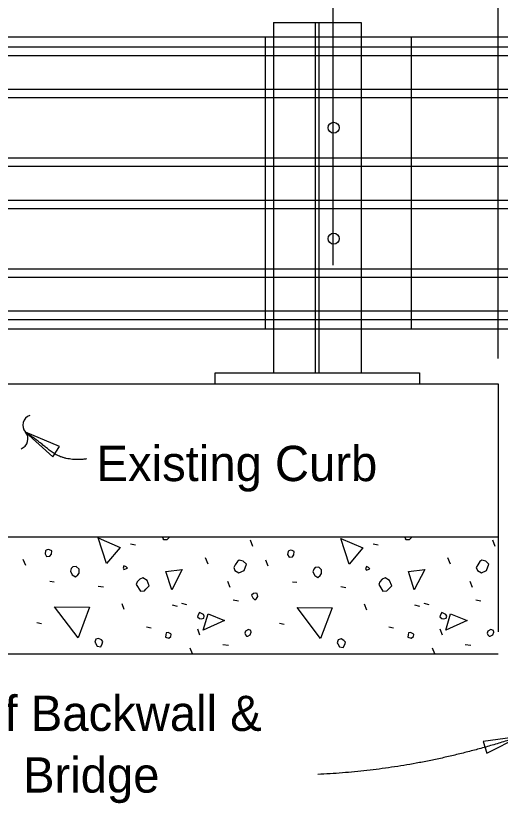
# Model space of a CAD drawing. Extents: x 21526.6 to 21595.9, y 56117 to 56157.3.
# Drawn here: x 21532.854 to 21535.621, y 56132.816 to 56137.312 of the extents above; entities that cross this region are included whole.
import ezdxf

# ---------------------------------------------------------------- set-up
doc = ezdxf.new("R2010")
doc.units = 0
for name, color, linetype in [('AdhocPoint_dp', 7, 'Continuous'), ('Border', 7, 'Continuous'), ('Patterning', 7, 'Continuous'), ('PlotBorder_dp', 7, 'Continuous'), ('SheetBorder_dp', 7, 'Continuous'), ('TextMisc', 7, 'Continuous')]:
    doc.layers.add(name, color=color, linetype=linetype)

msp = doc.modelspace()

# ---------------------------------------------------------------- linework, layer by layer
at = {"layer": 'AdhocPoint_dp'}
for p, q in [((21527.2426, 56135.21), (21535.6096, 56135.21)), ((21535.6096, 56135.2099), (21535.6096, 56133.7934)), ((21535.6096, 56134.335), (21527.2426, 56134.335)), ((21527.2426, 56133.6684), (21535.6096, 56133.6684))]:
    msp.add_line(p, q, dxfattribs=at)
at = {"layer": 'Patterning'}
for p, q in [((21534.6672, 56135.8883), (21534.6672, 56140.7989)), ((21534.2788, 56137.1891), (21534.2788, 56135.5224)), ((21535.1121, 56137.1891), (21535.1121, 56135.5224)), ((21534.1592, 56137.1336), (21541.6829, 56137.1336)), ((21534.1592, 56137.0854), (21541.6829, 56137.0854)), ((21534.1592, 56136.8926), (21541.6829, 56136.8926)), ((21534.1592, 56136.8444), (21541.6829, 56136.8444)), ((21534.1592, 56136.5004), (21541.6829, 56136.5004)), ((21534.1592, 56136.4522), (21541.6829, 56136.4522)), ((21534.1592, 56136.2594), (21541.6829, 56136.2594)), ((21534.1592, 56136.2112), (21541.6829, 56136.2112)), ((21534.1592, 56135.8673), (21541.6829, 56135.8673)), ((21534.1592, 56135.8191), (21541.6829, 56135.8191)), ((21534.1592, 56135.6262), (21541.6829, 56135.6262)), ((21534.1592, 56135.578), (21541.6829, 56135.578)), ((21533.5102, 56134.2973), (21533.5385, 56134.2902)), ((21534.2085, 56134.2814), (21534.1943, 56134.3167)), ((21534.8945, 56134.2973), (21534.9228, 56134.2902)), ((21535.5928, 56134.2814), (21535.5786, 56134.3167)), ((21532.9116, 56134.1724), (21532.8974, 56134.2077)), ((21533.9522, 56134.1806), (21533.938, 56134.216)), ((21534.2962, 56134.1689), (21534.2821, 56134.2042)), ((21535.3364, 56134.1806), (21535.3223, 56134.216)), ((21533.0495, 56134.084), (21533.0742, 56134.0805)), ((21534.0777, 56134.048), (21534.0653, 56134.0816)), ((21534.4341, 56134.0805), (21534.4589, 56134.0769)), ((21535.462, 56134.048), (21535.4496, 56134.0816)), ((21533.3252, 56134.0557), (21533.3553, 56134.0504)), ((21534.7099, 56134.0522), (21534.74, 56134.0469)), ((21534.0965, 56133.9762), (21534.1265, 56133.9709)), ((21535.4808, 56133.9762), (21535.5108, 56133.9709)), ((21533.4737, 56133.9214), (21533.4613, 56133.955)), ((21533.7477, 56133.9479), (21533.776, 56133.9408)), ((21533.8001, 56133.9579), (21533.8284, 56133.9508)), ((21534.8584, 56133.9178), (21534.846, 56133.9514)), ((21535.132, 56133.9479), (21535.1603, 56133.9408)), ((21535.1844, 56133.9579), (21535.2127, 56133.9508)), ((21532.9752, 56133.8471), (21533.0017, 56133.8418)), ((21534.3599, 56133.8436), (21534.3864, 56133.8383)), ((21533.601, 56133.8224), (21533.6275, 56133.8171)), ((21533.9062, 56133.7753), (21533.8938, 56133.8089)), ((21534.9853, 56133.8224), (21535.0118, 56133.8171)), ((21535.2905, 56133.7753), (21535.2781, 56133.8089)), ((21534.0364, 56133.7216), (21534.0682, 56133.7181)), ((21535.4207, 56133.7216), (21535.4525, 56133.7181)), ((21533.8627, 56133.6684), (21533.8496, 56133.701)), ((21535.247, 56133.6684), (21535.2339, 56133.701))]:
    msp.add_line(p, q, dxfattribs=at)
for points in [[(21533.373, 56134.1848), (21533.3252, 56134.3315), (21533.4507, 56134.2767), (21533.373, 56134.1848)], [(21533.6927, 56134.335), (21533.6923, 56134.3344), (21533.6976, 56134.322), (21533.6941, 56134.3256)], [(21533.6976, 56134.322), (21533.7188, 56134.322), (21533.7294, 56134.3326), (21533.7288, 56134.335)], [(21535.077, 56134.335), (21535.0766, 56134.3344), (21535.0819, 56134.322), (21535.0784, 56134.3256)], [(21535.0819, 56134.322), (21535.1031, 56134.322), (21535.1137, 56134.3326), (21535.1131, 56134.335)], [(21534.7576, 56134.1812), (21534.7099, 56134.328), (21534.8354, 56134.2731), (21534.7576, 56134.1812)], [(21533.0212, 56134.2396), (21533.03, 56134.2237), (21533.0495, 56134.2254), (21533.0583, 56134.2378), (21533.0601, 56134.2572), (21533.0477, 56134.2625), (21533.0389, 56134.2643), (21533.0282, 56134.2608), (21533.0247, 56134.2572), (21533.0212, 56134.2396)], [(21534.4059, 56134.236), (21534.4147, 56134.2201), (21534.4341, 56134.2219), (21534.443, 56134.2343), (21534.4447, 56134.2537), (21534.4324, 56134.259), (21534.4235, 56134.2608), (21534.4129, 56134.2572), (21534.4094, 56134.2537), (21534.4059, 56134.236)], [(21534.106, 56134.1435), (21534.1289, 56134.1311), (21534.159, 56134.1435), (21534.1714, 56134.1806), (21534.1537, 56134.1983), (21534.1307, 56134.2036), (21534.1201, 56134.1965), (21534.1077, 56134.1771), (21534.0989, 56134.1612), (21534.106, 56134.1435)], [(21535.4902, 56134.1435), (21535.5132, 56134.1311), (21535.5433, 56134.1435), (21535.5557, 56134.1806), (21535.538, 56134.1983), (21535.515, 56134.2036), (21535.5044, 56134.1965), (21535.492, 56134.1771), (21535.4832, 56134.1612), (21535.4902, 56134.1435)], [(21533.1661, 56134.1406), (21533.1767, 56134.1194), (21533.1944, 56134.1087), (21533.2086, 56134.1194), (21533.2156, 56134.13), (21533.2156, 56134.1512), (21533.1997, 56134.1671), (21533.1803, 56134.1653), (21533.1714, 56134.1565), (21533.1661, 56134.1406)], [(21533.472, 56134.1494), (21533.4914, 56134.1582), (21533.4843, 56134.1653), (21533.472, 56134.1706), (21533.4667, 56134.1582), (21533.472, 56134.1494)], [(21534.5508, 56134.137), (21534.5614, 56134.1158), (21534.5791, 56134.1052), (21534.5932, 56134.1158), (21534.6003, 56134.1264), (21534.6003, 56134.1476), (21534.5844, 56134.1635), (21534.5649, 56134.1618), (21534.5561, 56134.1529), (21534.5508, 56134.137)], [(21534.8566, 56134.1459), (21534.8761, 56134.1547), (21534.869, 56134.1618), (21534.8566, 56134.1671), (21534.8513, 56134.1547), (21534.8566, 56134.1459)], [(21533.7453, 56134.0339), (21533.7117, 56134.1382), (21533.8054, 56134.1505), (21533.7453, 56134.0339)], [(21535.1296, 56134.0339), (21535.096, 56134.1382), (21535.1897, 56134.1505), (21535.1296, 56134.0339)], [(21533.5427, 56134.0646), (21533.5656, 56134.0274), (21533.5886, 56134.0292), (21533.5975, 56134.038), (21533.6169, 56134.0575), (21533.6045, 56134.0875), (21533.5798, 56134.1017), (21533.5621, 56134.0946), (21533.548, 56134.0805), (21533.5427, 56134.0646)], [(21534.927, 56134.0646), (21534.9499, 56134.0274), (21534.9729, 56134.0292), (21534.9818, 56134.038), (21535.0012, 56134.0575), (21534.9888, 56134.0875), (21534.9641, 56134.1017), (21534.9464, 56134.0946), (21534.9323, 56134.0805), (21534.927, 56134.0646)], [(21534.2079, 56133.9885), (21534.2185, 56133.9779), (21534.2291, 56133.985), (21534.2361, 56133.9956), (21534.2326, 56134.0133), (21534.2238, 56134.0151), (21534.2114, 56134.0133), (21534.2008, 56134.0027), (21534.2079, 56133.9885)], [(21533.2103, 56133.7605), (21533.076, 56133.9373), (21533.2757, 56133.9355), (21533.2103, 56133.7605)], [(21534.595, 56133.757), (21534.4607, 56133.9337), (21534.6604, 56133.932), (21534.595, 56133.757)], [(21533.9027, 56133.8695), (21533.915, 56133.8677), (21533.9274, 56133.873), (21533.9309, 56133.8836), (21533.9256, 56133.8925), (21533.915, 56133.8995), (21533.9027, 56133.9048), (21533.8956, 56133.8907), (21533.8921, 56133.8801), (21533.9027, 56133.8695)], [(21533.925, 56133.8047), (21533.9533, 56133.8966), (21534.047, 56133.8595), (21533.925, 56133.8047)], [(21535.2869, 56133.8695), (21535.2993, 56133.8677), (21535.3117, 56133.873), (21535.3152, 56133.8836), (21535.3099, 56133.8925), (21535.2993, 56133.8995), (21535.2869, 56133.9048), (21535.2799, 56133.8907), (21535.2763, 56133.8801), (21535.2869, 56133.8695)], [(21535.3093, 56133.8047), (21535.3376, 56133.8966), (21535.4313, 56133.8595), (21535.3093, 56133.8047)], [(21534.1725, 56133.7693), (21534.1796, 56133.7693), (21534.1937, 56133.7764), (21534.199, 56133.7923), (21534.1973, 56133.8012), (21534.1831, 56133.8082), (21534.1654, 56133.7976), (21534.1619, 56133.787), (21534.1654, 56133.7764), (21534.1725, 56133.7693)], [(21535.5568, 56133.7693), (21535.5639, 56133.7693), (21535.578, 56133.7764), (21535.5833, 56133.7923), (21535.5815, 56133.8012), (21535.5674, 56133.8082), (21535.5497, 56133.7976), (21535.5462, 56133.787), (21535.5497, 56133.7764), (21535.5568, 56133.7693)], [(21533.3093, 56133.7287), (21533.3182, 56133.7128), (21533.3394, 56133.7092), (21533.3482, 56133.7251), (21533.3517, 56133.7393), (21533.3429, 56133.7481), (21533.327, 56133.757), (21533.3111, 56133.7517), (21533.3058, 56133.7357), (21533.3093, 56133.7287)], [(21533.7088, 56133.764), (21533.7283, 56133.7587), (21533.7407, 56133.7676), (21533.7424, 56133.7799), (21533.7389, 56133.7835), (21533.7247, 56133.7905), (21533.7124, 56133.7888), (21533.7106, 56133.7764), (21533.7088, 56133.764)], [(21534.694, 56133.7251), (21534.7028, 56133.7092), (21534.724, 56133.7057), (21534.7329, 56133.7216), (21534.7364, 56133.7357), (21534.7276, 56133.7446), (21534.7117, 56133.7534), (21534.6958, 56133.7481), (21534.6905, 56133.7322), (21534.694, 56133.7251)], [(21535.0931, 56133.764), (21535.1126, 56133.7587), (21535.1249, 56133.7676), (21535.1267, 56133.7799), (21535.1232, 56133.7835), (21535.109, 56133.7905), (21535.0967, 56133.7888), (21535.0949, 56133.7764), (21535.0931, 56133.764)]]:
    msp.add_lwpolyline(points, dxfattribs=at)
at = {"layer": 'PlotBorder_dp'}
msp.add_line((21535.6097, 56135.3555), (21535.6097, 56138.5276), dxfattribs=at)
for points in [[(21532.9092, 56134.934), (21533.0667, 56134.7933), (21533.1043, 56134.8531)], [(21535.7321, 56133.1961), (21535.5227, 56133.1687), (21535.5434, 56133.1013)]]:
    msp.add_lwpolyline(points, close=True, dxfattribs=at)
for centre, start, end in [((21532.9542, 56134.974), 109.3911, 221.1183), ((21532.8644, 56134.8956), 289.3911, 41.1183)]:
    msp.add_arc(centre, 0.0596, start, end, dxfattribs=at)
for points in [[(21533.2579, 56134.7814), (21533.1271, 56134.7638), (21532.9641, 56134.8995), (21532.9092, 56134.934)], [(21535.7321, 56133.1961), (21535.1554, 56133.0053), (21534.5787, 56132.9803)]]:
    msp.add_open_spline(points, degree=2, dxfattribs=at)
at = {"layer": 'SheetBorder_dp'}
for p, q in [((21534.5655, 56135.2724), (21534.5655, 56137.2724)), ((21534.5863, 56135.2724), (21534.5863, 56137.2724)), ((21541.6829, 56137.1892), (21534.1592, 56137.1892)), ((21534.3259, 56137.1892), (21534.3259, 56135.5224)), ((21534.8259, 56137.1892), (21534.8259, 56135.5225)), ((21541.6829, 56135.5225), (21534.1592, 56135.5225))]:
    msp.add_line(p, q, dxfattribs=at)
at = {"layer": 'TextMisc'}
for p, q in [((21534.3259, 56137.2724), (21534.8259, 56137.2724)), ((21534.3259, 56137.2724), (21534.3259, 56137.1891)), ((21534.8259, 56137.2724), (21534.8259, 56137.1891)), ((21534.2788, 56137.1892), (21527.2426, 56137.1892)), ((21527.2426, 56137.1336), (21534.2788, 56137.1336)), ((21527.2426, 56137.0854), (21534.2788, 56137.0854)), ((21527.2426, 56136.8926), (21534.2788, 56136.8926)), ((21527.2426, 56136.8444), (21534.2788, 56136.8444)), ((21527.2426, 56136.5004), (21534.2788, 56136.5004)), ((21527.2426, 56136.4522), (21534.2788, 56136.4522)), ((21527.2426, 56136.2594), (21534.2788, 56136.2594)), ((21527.2426, 56136.2112), (21534.2788, 56136.2112)), ((21527.2426, 56135.8673), (21534.2788, 56135.8673)), ((21527.2426, 56135.8191), (21534.2788, 56135.8191)), ((21527.2426, 56135.6262), (21534.2788, 56135.6262)), ((21527.2426, 56135.578), (21534.2788, 56135.578)), ((21534.2788, 56135.5225), (21527.2426, 56135.5225)), ((21534.3259, 56135.5224), (21534.3259, 56135.2724)), ((21534.8259, 56135.5225), (21534.8259, 56135.2724)), ((21533.9926, 56135.2724), (21535.1592, 56135.2724)), ((21533.9926, 56135.2099), (21533.9926, 56135.2724)), ((21534.3259, 56135.2724), (21534.8259, 56135.2724)), ((21535.1592, 56135.2724), (21535.1592, 56135.2099)), ((21533.9926, 56135.2099), (21535.1592, 56135.2099))]:
    msp.add_line(p, q, dxfattribs=at)
for centre in [(21534.6696, 56136.6723), (21534.6696, 56136.0392)]:
    msp.add_circle(centre, 0.0312, dxfattribs=at)

# ---------------------------------------------------------------- texts
at = {"layer": 'Border'}
msp.add_text('Existing Curb', height=0.2016, dxfattribs=at).set_placement((21533.3155, 56134.6548))
at = {"layer": 'PlotBorder_dp'}
for s, p in [('Front Face of Backwall &', (21531.262, 56133.2284)), ('Begin or End Bridge', (21531.262, 56132.8764))]:
    msp.add_text(s, height=0.2016, dxfattribs=at).set_placement(p)

doc.saveas('drawing.dxf')
